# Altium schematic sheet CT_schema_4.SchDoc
size 282 x 169 mm
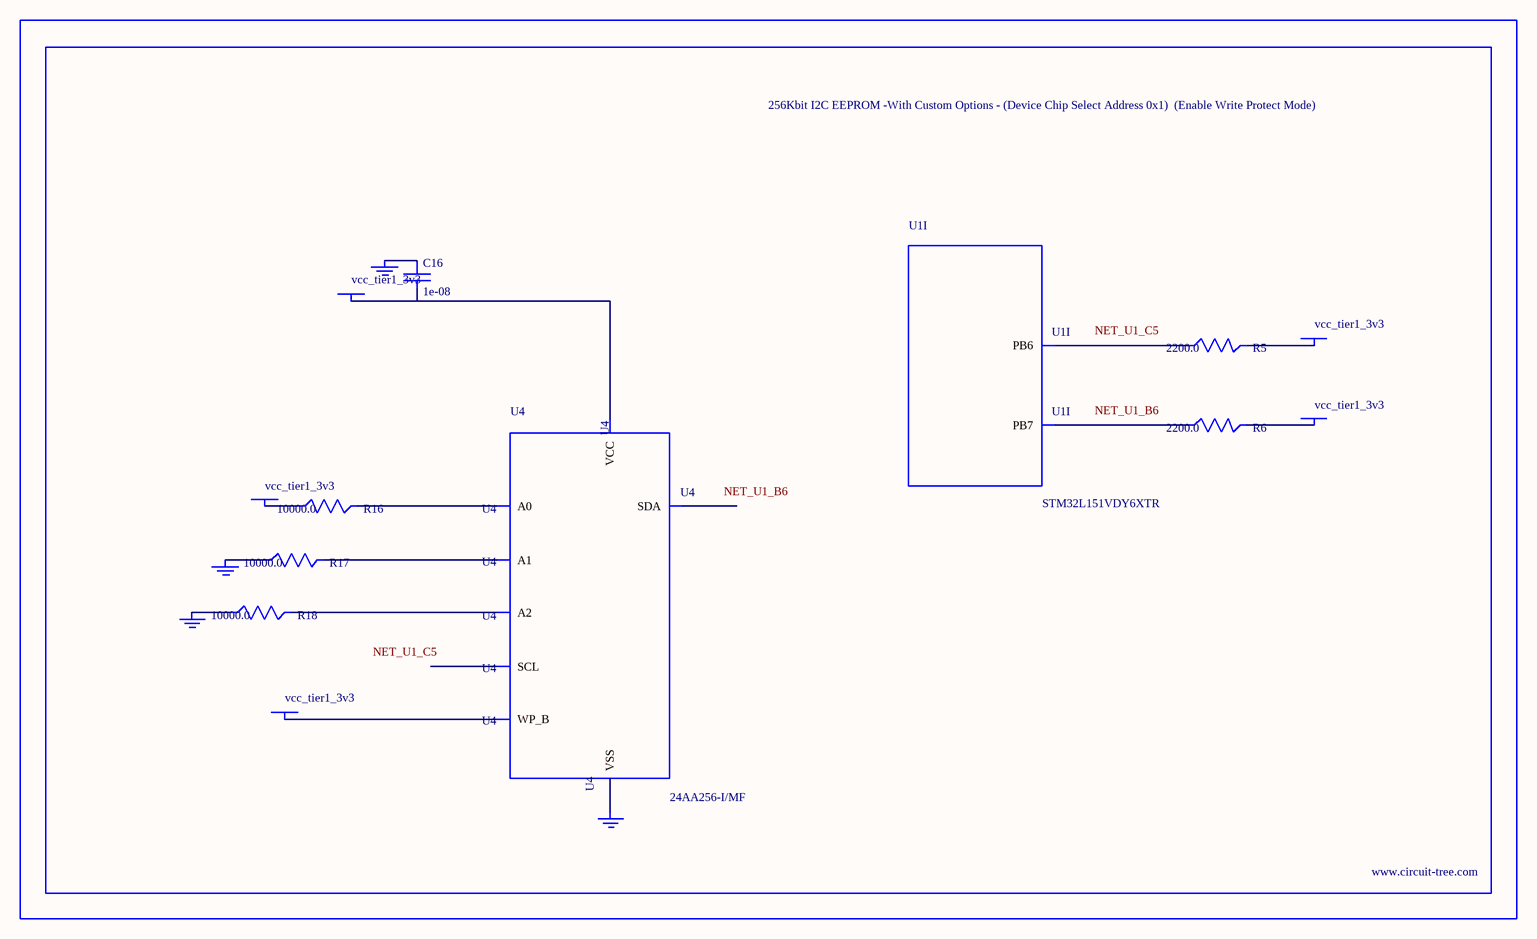
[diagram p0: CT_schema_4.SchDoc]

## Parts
BORDER3  (no value)
C16  1e-08  [C0402]
GND_INSTANCE_3_0  (no value)
GND_INSTANCE_3_1  (no value)
GND_INSTANCE_3_2  (no value)
GND_INSTANCE_3_3  (no value)
POWER_INSTANCE_3_0  vcc_tier1_3v3
POWER_INSTANCE_3_1  vcc_tier1_3v3
POWER_INSTANCE_3_2  vcc_tier1_3v3
POWER_INSTANCE_3_3  vcc_tier1_3v3
POWER_INSTANCE_3_4  vcc_tier1_3v3
R5  2200.0  [R0603]
R6  2200.0  [R0603]
R16  10000.0  [R0603]
R17  10000.0  [R0603]
R18  10000.0  [R0603]
U1  STM32L151VDY6XTR  [WLCSP104]  (part I of 10)
U4  24AA256-I/MF  [DFN8-S]

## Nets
NetC16_1: C16.1 GND_INSTANCE_3_2.0(GND)
NetC16_2: C16.2 POWER_INSTANCE_3_2.0(PWR) U4.8(VCC)
NetGND_INSTANCE_3_0_0: GND_INSTANCE_3_0.0(GND) R17.1
NetGND_INSTANCE_3_1_0: GND_INSTANCE_3_1.0(GND) R18.1
NetGND_INSTANCE_3_3_0: GND_INSTANCE_3_3.0(GND) U4.4(VSS)
NetPOWER_INSTANCE_3_0_0: POWER_INSTANCE_3_0.0(PWR) R16.1
NetPOWER_INSTANCE_3_1_0: POWER_INSTANCE_3_1.0(PWR) U4.7(WP_B)
NetPOWER_INSTANCE_3_3_0: POWER_INSTANCE_3_3.0(PWR) R5.2
NetPOWER_INSTANCE_3_4_0: POWER_INSTANCE_3_4.0(PWR) R6.2
NetR5_1: R5.1 U1.C5(PB6)
NetR6_1: R6.1 U1.B6(PB7)
NetR16_2: R16.2 U4.1(A0)
NetR17_2: R17.2 U4.2(A1)
NetR18_2: R18.2 U4.3(A2)

Not connected (* = marked no-connect by the designer): U4 5(SDA) 6(SCL)

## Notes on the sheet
- Labels drawn without touching a wire or pin: NET_U1_B6, NET_U1_C5

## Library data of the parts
BORDER3 = BORDER_PAGE3
C16 = C0402C103K3RAC
GND_INSTANCE_3_0-GND_INSTANCE_3_3 = GND
POWER_INSTANCE_3_0-POWER_INSTANCE_3_4 = PWR
R5 R6 = RC0603JR-072K2L
R16-R18 = RC0603JR-0710KL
